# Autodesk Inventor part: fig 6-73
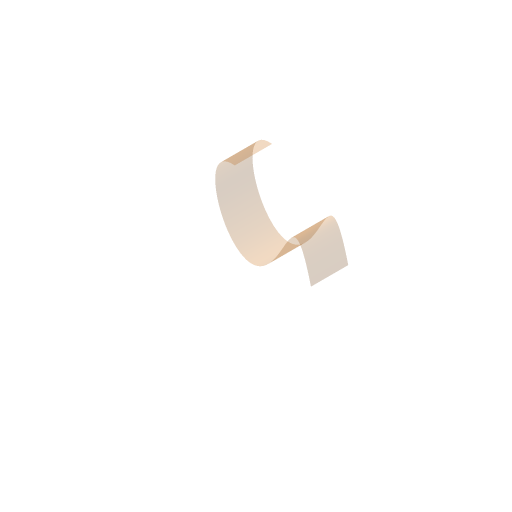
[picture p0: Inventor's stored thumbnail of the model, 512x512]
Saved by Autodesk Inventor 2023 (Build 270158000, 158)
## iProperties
Part Number: fig 6-73
Document SubType Name: Modeling
Created: 2002-12
Designer: deepak
Density: 1 g/cm^3
Material: Generic
Appearance: Default
Control State: 0
Master: False
Checked Out: False
Shininess: 64.0
Length Units: 11269
Angle Units: 11279
Time Units: 11290
Mass Units: 11283
Length Display Precision: 3
Angle Display Precision: 2
Compacted: True
Density: 0.0
Volumn: 0.0
Area: 0.0
PropertySet Name: Model Information
Author: deepak
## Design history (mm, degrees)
sketch "Sketch1"
  geometry: 5 further points
  constraints: 5 other
extrude_surface "ExtrusionSrf1" sketch "Sketch1" dims "d0" = 20, "d1" = 0
body "Srf1"
